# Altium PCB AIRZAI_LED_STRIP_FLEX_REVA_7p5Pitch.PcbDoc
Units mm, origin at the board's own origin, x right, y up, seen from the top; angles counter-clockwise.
Board outline 158.45 x 20.7 mm, 2 copper layers (Top Layer, Bottom Layer); 39 components, 40 nets, 198 pads, 42 vias.
Unrouted connection lines stored in the file: 63.
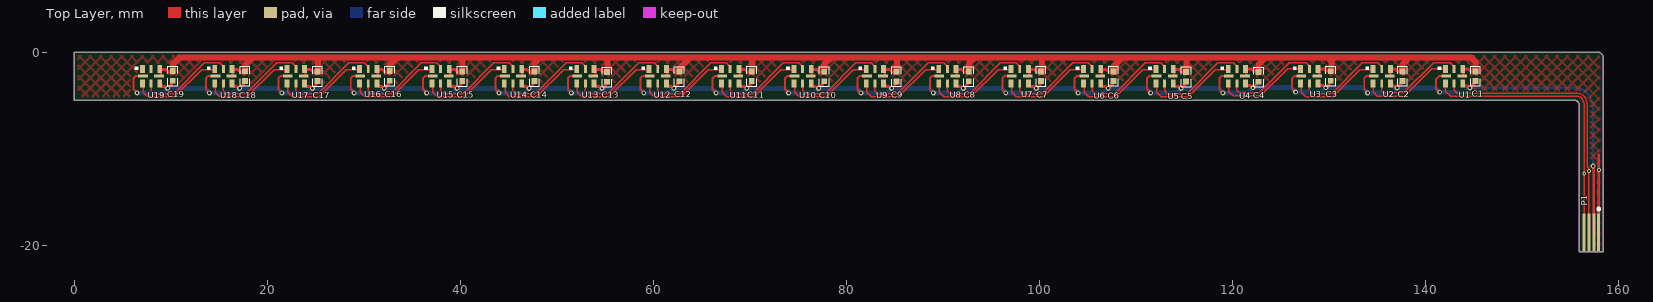
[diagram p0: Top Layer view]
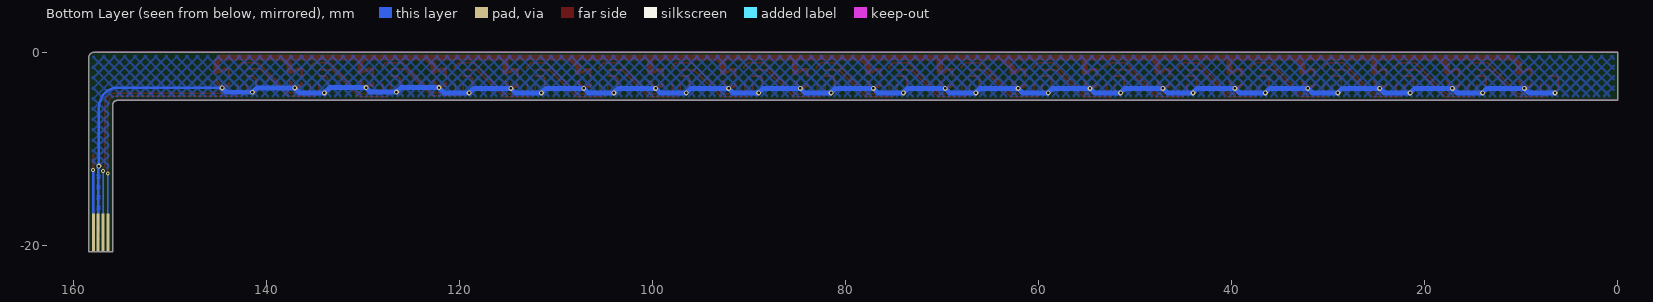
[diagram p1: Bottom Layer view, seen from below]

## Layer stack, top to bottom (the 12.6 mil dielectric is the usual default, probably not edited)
Top Solder: solder mask 0.0102, Solder Resist, Dk 3.5
Top Layer: signal copper 0.0356
Dielectric 1: dielectric 0.32, FR-4, Dk 4.8
Bottom Layer: signal copper 0.0356
Bottom Solder: solder mask 0.0102, Solder Resist, Dk 3.5

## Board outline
0,-5 0,0 157.814,0 cw(c157.814,-0.636) 158.45,-0.636 158.45,-20.7 155.95,-20.7 155.95,-5.5 ccw(c155.45,-5.5) 155.45,-5
board region "Layer Stack Region 1": 158.45,-14.093 158.45,-20.7 155.95,-20.7 155.95,-14.093
board region "Layer Stack Region 1": 155.95,-13.28 155.95,-5.5 155.94,-5.402 155.866,-5.222 155.728,-5.084 155.548,-5.01 155.45,-5 0,-5 0,0 157.814,0 157.941,0 158.174,-0.097 158.353,-0.276 158.45,-0.509 158.45,-0.636 158.45,-13.28
board region "Layer Stack Region 2": 155.95,-14.093 155.95,-13.28 158.45,-13.28 158.45,-14.093

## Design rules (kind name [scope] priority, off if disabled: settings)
Clearance Clearance_polygon_5V [OnLayer('Keep-Out Layer') vs (InNet('+5V') AND InPolygon)] p1: gap=0.254 ignorepadtopadclearanceinfootprint=FALSE
Clearance Clearance_POLYGON_KEEPOUT [(OnLayer('Keep-Out Layer')) vs (InNet('GND') AND InPolygon)] p2: gap=0.254 ignorepadtopadclearanceinfootprint=FALSE
Clearance [All] p3: gap=0.152 ignorepadtopadclearanceinfootprint=FALSE
MinimumSolderMaskSliver [All] p1: minsoldermaskwidth=0.025
PolygonConnect [All] p1: connectstyle=Direct reliefconductorwidth=0.254 reliefentries=4 polygonreliefangle="90 Angle" airgapwidth=0.254
RoomDefinition AIRZAI_LED_STRIP_FLEX_REVA_7p5Pitch [InComponentClass('AIRZAI_LED_STRIP_FLEX_REVA_7p5Pitch')] p1: confinementstyle=ConfineIn formatcopy=TRUE lockcomponents=FALSE outline -106.277,-135.212 266.087,-135.212 266.087,108.628 -106.277,108.628
RoutingVias [All] p1: holewidth=0.711 width=1.27 viastyle="Through Hole" minholewidth=0.203 minwidth=0.406 maxholewidth=0.711 maxwidth=1.27
SilkToSilkClearance [All] p1: silktosilkclearance=0.025
SilkToSolderMaskClearance [IsPad] p1: minsilkscreentomaskgap=0.051 clearancetoexposedcopper=TRUE
SolderMaskExpansion [All] p1: expansion=0.102
UnRoutedNet [All] p1: checkbadconnections=TRUE
Width [All] p1: maxlimit=2.54 minlimit=0.152 preferedwidth=0.254
26 further rules are at their usual default settings.

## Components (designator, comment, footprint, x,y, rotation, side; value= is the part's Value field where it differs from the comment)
C1 "0.1µF" 0402CAP 145.186,-2.5 r270 top
C2 "0.1µF" 0402CAP 137.64,-2.5 r270 top
C3 "0.1µF" 0402CAP 130.186,-2.483 r270 top
C4 "0.1µF" 0402CAP 122.724,-2.576 r270 top
C5 "0.1µF" 0402CAP 115.214,-2.559 r270 top
C6 "0.1µF" 0402CAP 107.686,-2.5 r270 top
C7 "0.1µF" 0402CAP 100.186,-2.508 r270 top
C8 "0.1µF" 0402CAP 92.686,-2.525 r270 top
C9 "0.1µF" 0402CAP 85.212,-2.538 r270 top
C10 "0.1µF" 0402CAP 77.712,-2.533 r270 top
C11 "0.1µF" 0402CAP 70.204,-2.508 r270 top
C12 "0.1µF" 0402CAP 62.712,-2.521 r270 top
C13 "0.1µF" 0402CAP 55.212,-2.576 r270 top
C14 "0.1µF" 0402CAP 47.697,-2.508 r270 top
C15 "0.1µF" 0402CAP 40.212,-2.508 r270 top
C16 "0.1µF" 0402CAP 32.696,-2.469 r270 top
C17 "0.1µF" 0402CAP 25.212,-2.508 r270 top
C18 "0.1µF" 0402CAP 17.712,-2.495 r270 top
C19 "0.1µF" 0402CAP 10.223,-2.471 r270 top
P1 "Header 4" FFC_4PADS 157.2,-18.7 r0 top
U1 "APA102-2020-256-8" APA102–2020 142.977,-2.5 r270 top
U2 "APA102-2020-256-8" APA102–2020 135.477,-2.5 r270 top
U3 "APA102-2020-256-8" APA102–2020 127.977,-2.5 r270 top
U4 "APA102-2020-256-8" APA102–2020 120.477,-2.5 r270 top
U5 "APA102-2020-256-8" APA102–2020 112.979,-2.5 r270 top
U6 "APA102-2020-256-8" APA102–2020 105.477,-2.5 r270 top
U7 "APA102-2020-256-8" APA102–2020 97.977,-2.5 r270 top
U8 "APA102-2020-256-8" APA102–2020 90.477,-2.5 r270 top
U9 "APA102-2020-256-8" APA102–2020 82.977,-2.5 r270 top
U10 "APA102-2020-256-8" APA102–2020 75.477,-2.5 r270 top
U11 "APA102-2020-256-8" APA102–2020 67.977,-2.5 r270 top
U12 "APA102-2020-256-8" APA102–2020 60.477,-2.5 r270 top
U13 "APA102-2020-256-8" APA102–2020 52.977,-2.5 r270 top
U14 "APA102-2020-256-8" APA102–2020 45.477,-2.5 r270 top
U15 "APA102-2020-256-8" APA102–2020 37.977,-2.5 r270 top
U16 "APA102-2020-256-8" APA102–2020 30.477,-2.5 r270 top
U17 "APA102-2020-256-8" APA102–2020 22.977,-2.5 r270 top
U18 "APA102-2020-256-8" APA102–2020 15.477,-2.5 r270 top
U19 "APA102-2020-256-8" APA102–2020 7.977,-2.5 r270 top

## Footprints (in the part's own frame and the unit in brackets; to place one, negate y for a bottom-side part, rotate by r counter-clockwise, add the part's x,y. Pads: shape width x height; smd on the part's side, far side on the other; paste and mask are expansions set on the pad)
0402CAP [mm] "Chip Capacitor, Body 1.1x0.5mm, IPC High Density"
  rect 0.6x0.6 smd: 1(-0.5,0) 2(0.5,0)
  silkscreen extent -1.02,-0.51 1.02,0.51, body extent -0.5,-0.3 0.5,0.3, height 0.19
APA102–2020 [mm]
  rect 0.8x0.5 smd: 1(-0.75,0.9) 3(-0.75,-0.9) 4(0.75,-0.9) 6(0.75,0.9)
  rect 0.8x0.3 smd: 2(-0.75,0) 5(0.75,0)
  rect 0.3x1 smd: 7(0,-0.83) 8(0,0.83)
  silkscreen extent -1.02,-1.7 -0.63,-1.32, body extent -1,-1 1,1, height 0.94
FFC_4PADS [mm] "(0.50mm"
  rect 0.3x4 smd: 1(0.75,0) 2(0.25,0) 3(-0.25,0) 4(-0.75,0)
  rect 0.3x4 smd far side: 1(0.75,0) 2(0.25,0) 3(-0.25,0) 4(-0.75,0)
  silkscreen extent 0.64,2.31 0.89,2.56

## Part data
C1 C2 C3 C4 C5 C6 C7 C8 C9 C10 C11 C12 C13 C14 C15 C16 C17 C18 C19: library part C0402-100n, "Capacitor, X7R, ±10%", Case-EIA=0402, Case-Metric=1005, Manufacturer=TDK, Manufacturer Part Number=C1005X7R1C104K, Rated Voltage="16 V", Supplier Part Number 1=445-4952-2-ND, Tolerance=±20%
P1: "Header, 4-Pin"
U1 U2 U3 U4 U5 U6 U7 U8 U9 U10 U11 U12 U13 U14 U15 U16 U17 U18 U19: "DotStar Micro LEDs", Package="SOIC-20 Adafruit Industries"

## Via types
v1: diameter 0.508, hole 0.254, Top Layer to Bottom Layer, tented both sides, 39 vias
v2: diameter 0.406, hole 0.203, Top Layer to Bottom Layer, tented both sides, 3 vias

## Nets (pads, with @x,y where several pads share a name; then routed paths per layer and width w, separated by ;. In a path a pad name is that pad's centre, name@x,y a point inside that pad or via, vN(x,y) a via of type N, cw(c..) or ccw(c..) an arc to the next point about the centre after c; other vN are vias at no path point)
+5V: C1.1 C2.1 C3.1 C4.1 C5.1 C6.1 C7.1 C8.1 C9.1 C10.1 C11.1 C12.1 C13.1 C14.1 C15.1 C16.1 C17.1 C18.1 C19.1 P1.1 U1.1 U1.8 U2.1 U2.8 U3.1 U3.8 U4.1 U4.8 U5.1 U5.8 U6.1 U6.8 U7.1 U7.8 U8.1 U8.8 U9.1 U9.8 U10.1 U10.8 U11.1 U11.8 U12.1 U12.8 U13.1 U13.8 U14.1 U14.8 U15.1 U15.8 U16.1 U16.8 U17.1 U17.8 U18.1 U18.8 U19.1 U19.8 | length 236
  Top Layer w0.254: U19.8@8.976,-2.46 U19.1@8.976,-1.809 ; U18.8@16.449,-2.5 U18.1@16.449,-1.809 ; U17.8@23.976,-2.46 U17.1@23.976,-1.809 ; U16.8@31.446,-2.5 U16.1@31.446,-1.809 ; U15.8@38.976,-2.46 U15.1@38.976,-1.809 ; U14.8@46.447,-2.5 U14.1@46.447,-1.809 ; U13.8@53.976,-2.46 U13.1@53.976,-1.809 ; U12.8@61.449,-2.5 U12.1@61.449,-1.809 ; U11.8@68.976,-2.46 U11.1@68.976,-1.809 ; U10.8@76.449,-2.5 U10.1@76.449,-1.809 ; U9.8@83.976,-2.46 U9.1@83.976,-1.809 ; U8.8@91.449,-2.5 U8.1@91.449,-1.809 ; U7.8@98.976,-2.46 U7.1@98.976,-1.809 ; U6.8@106.449,-2.5 U6.1@106.449,-1.809 ; U5.8@113.979,-2.46 U5.1@113.979,-1.809 ; U4.8@121.379,-2.482 121.426,-2.482 121.449,-2.459 U4.1@121.449,-1.732 ; U3.8@128.976,-2.482 128.999,-2.459 U3.1@128.999,-1.732 ; U2.8 136.354,-2.5 136.377,-2.477 U2.1 ; U1.8@143.9,-2.5 143.923,-2.477 U1.1@143.923,-1.75 ; P1.1@157.95,-18.7 157.95,-12.353 157.953,-12.351 157.953,-12.243 v2(157.982,-12.214) 157.982,-10.613
  Top Layer w0.305: U19.1@8.976,-1.809 9.498,-1.809 9.748,-2.059 C19.1@10.262,-2.059 ; U18.1@16.449,-1.809 16.948,-1.809 17.198,-2.059 C18.1@17.712,-2.059 ; U17.1@23.976,-1.809 24.498,-1.809 24.748,-2.059 C17.1@25.262,-2.059 ; U16.1@31.446,-1.809 31.945,-1.809 32.195,-2.059 C16.1@32.71,-2.059 ; U15.1@38.976,-1.809 39.498,-1.809 39.748,-2.059 C15.1@40.262,-2.059 ; U14.1@46.447,-1.809 46.946,-1.809 47.196,-2.059 C14.1@47.711,-2.059 ; U13.1@53.976,-1.809 54.498,-1.809 54.748,-2.059 C13.1@55.262,-2.059 ; U12.1@61.449,-1.809 61.948,-1.809 62.198,-2.059 C12.1@62.712,-2.059 ; U11.1@68.976,-1.809 69.498,-1.809 69.748,-2.059 C11.1@70.262,-2.059 ; U10.1@76.449,-1.809 76.948,-1.809 77.198,-2.059 C10.1@77.712,-2.059 ; U9.1@83.976,-1.809 84.498,-1.809 84.748,-2.059 C9.1@85.262,-2.059 ; U8.1@91.449,-1.809 91.948,-1.809 92.198,-2.059 C8.1@92.712,-2.059 ; U7.1@98.976,-1.809 99.498,-1.809 99.748,-2.059 C7.1@100.262,-2.059 ; U6.1@106.449,-1.809 106.948,-1.809 107.198,-2.059 C6.1@107.712,-2.059 ; U5.1@113.979,-1.809 114.501,-1.809 114.751,-2.059 C5.1@115.265,-2.059 ; U4.1@121.449,-1.732 121.948,-1.732 122.198,-1.982 C4.1@122.712,-1.982 ; U3.1@128.999,-1.732 129.498,-1.732 129.748,-1.982 C3.1@130.262,-1.982 ; U2.1 136.876,-1.75 137.126,-2 C2.1 ; U1.1@143.923,-1.75 144.422,-1.75 144.672,-2 C1.1
  Top Layer w0.635: C19.1@10.262,-2.059 10.262,-1.19 10.264,-1.19 10.879,-0.575 115.265,-0.575 ; C18.1@17.712,-2.059 17.712,-1.322 18.459,-0.575 ; 25.114,-0.575 25.262,-0.723 C17.1@25.262,-2.059 ; C16.1@32.71,-2.059 32.71,-1.314 33.449,-0.575 ; 35.951,-0.575 40.124,-0.575 40.262,-0.713 C15.1@40.262,-2.059 ; C14.1@47.711,-2.059 47.711,-1.134 48.27,-0.575 49.611,-0.575 ; 52.112,-0.575 55.206,-0.575 55.262,-0.632 C13.1@55.262,-2.059 ; C12.1@62.712,-2.059 62.712,-1.698 63.835,-0.575 ; 66.335,-0.575 70.08,-0.575 ; C11.1@70.262,-2.059 70.262,-0.758 70.08,-0.575 ; 70.262,-0.575 70.08,-0.575 ; C10.1@77.712,-2.059 77.712,-1.287 78.424,-0.575 ; C9.1@85.262,-2.059 85.262,-0.575 ; C8.1@92.712,-2.059 92.712,-1.183 93.319,-0.575 ; C7.1@100.262,-2.059 100.262,-0.711 100.127,-0.575 ; C6.1@107.712,-2.059 107.712,-1.47 108.606,-0.575 ; C5.1@115.265,-2.059 115.265,-0.575 ; C4.1@122.712,-1.982 122.712,-1.298 123.318,-0.691 ; 129.862,-0.575 130.262,-0.975 C3.1@130.262,-1.982 ; C2.1 137.64,-1.286 138.33,-0.595 138.31,-0.575 ; C1.1 145.186,-0.993 144.769,-0.575 115.265,-0.575 ; 100.127,-0.575 98.053,-0.575 100.127,-0.575
  Bottom Layer w0.254: P1.1@157.95,-18.7 157.95,-12.353 157.953,-12.351 157.953,-12.248 157.95,-12.246 v2(157.982,-12.214)
GND: C1.2 C2.2 C3.2 C4.2 C5.2 C6.2 C7.2 C8.2 C9.2 C10.2 C11.2 C12.2 C13.2 C14.2 C15.2 C16.2 C17.2 C18.2 C19.2 P1.2 U1.6 U1.7 U2.6 U2.7 U3.6 U3.7 U4.6 U4.7 U5.6 U5.7 U6.6 U6.7 U7.6 U7.7 U8.6 U8.7 U9.6 U9.7 U10.6 U10.7 U11.6 U11.7 U12.6 U12.7 U13.6 U13.7 U14.6 U14.7 U15.6 U15.7 U16.6 U16.7 U17.6 U17.7 U18.6 U18.7 U19.6 U19.7 | length 266.7
  Top Layer w0.203: v1(6.523,-4.22) 6.165,-3.863 6.165,-2.7 6.365,-2.5 U19.7 ; v1(14.023,-4.22) 13.665,-3.863 13.665,-2.7 13.865,-2.5 U18.7 ; v1(21.523,-4.22) 21.165,-3.863 21.165,-2.7 21.365,-2.5 U17.7 ; v1(29.023,-4.22) 28.665,-3.863 28.665,-2.7 28.865,-2.5 U16.7 ; v1(36.523,-4.22) 36.165,-3.863 36.165,-2.7 36.365,-2.5 U15.7 ; v1(44.023,-4.22) 43.665,-3.863 43.665,-2.7 43.865,-2.5 U14.7 ; v1(51.523,-4.22) 51.165,-3.863 51.165,-2.7 51.365,-2.5 U13.7 ; v1(59.023,-4.22) 58.665,-3.863 58.665,-2.7 58.865,-2.5 U12.7 ; v1(66.523,-4.22) 66.165,-3.863 66.165,-2.7 66.365,-2.5 U11.7 ; v1(74.023,-4.22) 73.665,-3.863 73.665,-2.7 73.865,-2.5 U10.7 ; v1(81.523,-4.22) 81.165,-3.863 81.165,-2.7 81.365,-2.5 U9.7 ; v1(89.023,-4.22) 88.665,-3.863 88.665,-2.7 88.865,-2.5 U8.7 ; v1(96.523,-4.22) 96.165,-3.863 96.165,-2.7 96.365,-2.5 U7.7 ; v1(104.023,-4.22) 103.665,-3.863 103.665,-2.7 103.865,-2.5 U6.7 ; v1(111.525,-4.22) 111.168,-3.863 111.168,-2.7 111.368,-2.5 U5.7 ; v1(119.023,-4.22) 118.665,-3.863 118.665,-2.7 118.865,-2.5 U4.7 ; v1(126.548,-4.144) 126.191,-3.787 126.191,-2.725 126.416,-2.5 U3.7@127.096,-2.5 ; v1(134.023,-4.22) 133.665,-3.863 133.665,-2.7 133.865,-2.5 U2.7 ; v1(141.472,-4.162) 141.115,-3.804 141.115,-2.813 141.427,-2.5 U1.7@142.037,-2.5
  Top Layer w0.254: v1@157.421,-11.856 v1(157.372,-11.807) 157.372,-12.061 157.45,-12.139 P1.2@157.45,-18.7
  Top Layer w0.305: U19.6@8.999,-3.309 8.999,-3.459 9.097,-3.556 9.431,-3.556 9.638,-3.763 v1(9.693,-3.763) 10.115,-3.342 10.115,-3.206 C19.2@10.262,-3.059 ; U18.6@16.449,-3.309 16.449,-3.459 16.546,-3.556 16.881,-3.556 17.088,-3.763 v1(17.143,-3.763) 17.564,-3.342 17.564,-3.206 C18.2@17.712,-3.059 ; U17.6@23.999,-3.309 23.999,-3.459 24.097,-3.556 24.431,-3.556 24.638,-3.763 v1(24.693,-3.763) 25.115,-3.342 25.115,-3.206 C17.2@25.262,-3.059 ; U16.6@31.446,-3.309 31.446,-3.459 31.544,-3.556 31.879,-3.556 32.086,-3.763 v1(32.141,-3.763) 32.562,-3.342 32.562,-3.206 C16.2@32.71,-3.059 ; U15.6@38.999,-3.309 38.999,-3.459 39.097,-3.556 39.431,-3.556 39.638,-3.763 v1(39.693,-3.763) 40.115,-3.342 40.115,-3.206 C15.2@40.262,-3.059 ; U14.6@46.447,-3.309 46.447,-3.459 46.545,-3.556 46.88,-3.556 47.087,-3.763 v1(47.142,-3.763) 47.563,-3.342 47.563,-3.206 C14.2@47.711,-3.059 ; U13.6@53.999,-3.309 53.999,-3.459 54.097,-3.556 54.431,-3.556 54.638,-3.763 v1(54.693,-3.763) 55.115,-3.342 55.115,-3.206 C13.2@55.262,-3.059 ; U12.6@61.449,-3.309 61.449,-3.459 61.546,-3.556 61.881,-3.556 62.088,-3.763 v1(62.143,-3.763) 62.564,-3.342 62.564,-3.206 C12.2@62.712,-3.059 ; U11.6@68.999,-3.309 68.999,-3.459 69.097,-3.556 69.431,-3.556 69.638,-3.763 v1(69.693,-3.763) 70.115,-3.342 70.115,-3.206 C11.2@70.262,-3.059 ; U10.6@76.449,-3.309 76.449,-3.459 76.546,-3.556 76.881,-3.556 77.088,-3.763 v1(77.143,-3.763) 77.564,-3.342 77.564,-3.206 C10.2@77.712,-3.059 ; U9.6@83.999,-3.309 83.999,-3.459 84.097,-3.556 84.431,-3.556 84.638,-3.763 v1(84.693,-3.763) 85.115,-3.342 85.115,-3.206 C9.2@85.262,-3.059 ; U8.6@91.449,-3.309 91.449,-3.459 91.546,-3.556 91.881,-3.556 92.088,-3.763 v1(92.143,-3.763) 92.564,-3.342 92.564,-3.206 C8.2@92.712,-3.059 ; U7.6@98.999,-3.309 98.999,-3.459 99.097,-3.556 99.431,-3.556 99.638,-3.763 v1(99.693,-3.763) 100.115,-3.342 100.115,-3.206 C7.2@100.262,-3.059 ; U6.6@106.449,-3.309 106.449,-3.459 106.546,-3.556 106.881,-3.556 107.088,-3.763 v1(107.143,-3.763) 107.564,-3.342 107.564,-3.206 C6.2@107.712,-3.059 ; U5.6@114.002,-3.309 114.002,-3.459 114.099,-3.556 114.434,-3.556 114.641,-3.763 v1(114.696,-3.763) 115.117,-3.342 115.117,-3.206 C5.2@115.265,-3.059 ; U4.6@121.449,-3.232 121.449,-3.382 121.546,-3.48 121.881,-3.48 122.088,-3.687 v1(122.143,-3.687) 122.564,-3.266 122.564,-3.13 C4.2@122.712,-2.982 ; U3.6@128.999,-3.232 128.999,-3.382 129.097,-3.48 129.431,-3.48 129.638,-3.687 v1(129.693,-3.687) 130.115,-3.266 130.115,-3.13 C3.2@130.262,-2.982 ; U2.6 136.377,-3.4 136.474,-3.498 136.809,-3.498 137.016,-3.705 v1(137.071,-3.705) 137.492,-3.283 137.492,-3.148 C2.2 ; U1.6@143.923,-3.25 143.923,-3.4 144.021,-3.498 144.355,-3.498 144.562,-3.705 v1(144.617,-3.705) 145.039,-3.283 145.039,-3.148 C1.2
  Bottom Layer w0.254: v1(144.617,-3.705) 155.498,-3.705 cw(c155.498,-5.466) 156.743,-4.22 cw(c155.225,-5.739) 157.372,-5.739 v1(157.372,-11.807) ; P1.2@157.45,-18.7 157.45,-12.064
  Bottom Layer w0.508: v1(6.523,-4.22) 9.236,-4.22 v1(9.693,-3.763) 13.565,-3.763 v1(14.023,-4.22) 16.686,-4.22 v1(17.143,-3.763) 21.065,-3.763 v1(21.523,-4.22) 24.236,-4.22 v1(24.693,-3.763) 28.565,-3.763 v1(29.023,-4.22) 31.683,-4.22 v1(32.141,-3.763) 36.065,-3.763 v1(36.523,-4.22) 39.236,-4.22 v1(39.693,-3.763) 43.565,-3.763 v1(44.023,-4.22) 46.684,-4.22 v1(47.142,-3.763) 51.065,-3.763 v1(51.523,-4.22) 54.236,-4.22 v1(54.693,-3.763) 58.565,-3.763 v1(59.023,-4.22) 61.686,-4.22 v1(62.143,-3.763) 66.065,-3.763 v1(66.523,-4.22) 69.236,-4.22 v1(69.693,-3.763) 73.565,-3.763 v1(74.023,-4.22) 76.686,-4.22 v1(77.143,-3.763) 81.065,-3.763 v1(81.523,-4.22) 84.236,-4.22 v1(84.693,-3.763) 88.565,-3.763 v1(89.023,-4.22) 91.686,-4.22 v1(92.143,-3.763) 96.065,-3.763 v1(96.523,-4.22) 99.236,-4.22 v1(99.693,-3.763) 103.565,-3.763 v1(104.023,-4.22) 106.686,-4.22 v1(107.143,-3.763) 111.068,-3.763 v1(111.525,-4.22) 114.239,-4.22 v1(114.696,-3.763) 118.565,-3.763 v1(119.023,-4.22) 121.61,-4.22 v1(122.143,-3.687) 126.091,-3.687 v1(126.548,-4.144) 129.236,-4.144 v1(129.693,-3.687) 133.489,-3.687 v1(134.023,-4.22) 136.555,-4.22 v1(137.071,-3.705) 141.015,-3.705 v1(141.472,-4.162) 144.16,-4.162 v1(144.617,-3.705)
LED_CLK_IN: P1.3 U1.5 | length 35
  Top Layer w0.152: U1.5 142.977,-3.965 143.301,-4.289 155.83,-4.289 cw(c155.83,-5.069) 156.382,-4.517 cw(c155.401,-5.499) 156.788,-5.499 156.788,-11.765 ccw(c157.135,-11.765) 156.89,-12.01 cw(c156.744,-12.156) 156.95,-12.156 v2(156.95,-12.315) P1.3@156.95,-18.7
  Bottom Layer w0.152: P1.3@156.95,-18.7 v2(156.95,-12.315)
LED_CLK_OUT1: U1.2 U2.5 | length 10
  Top Layer w0.152: U2.5 135.477,-4.031 135.684,-4.238 137.731,-4.238 140.848,-1.121 142.572,-1.121 142.977,-1.526 U1.2
LED_CLK_OUT2: U2.2 U3.5 | length 10.1
  Top Layer w0.152: U3.5@127.973,-3.25 127.973,-4.017 128.252,-4.297 130.3,-4.297 133.475,-1.121 135.089,-1.121 135.553,-1.585 U2.2@135.553,-1.75
LED_CLK_OUT3: U3.2 U4.5 | length 10.1
  Top Layer w0.152: U4.5 120.477,-3.941 120.756,-4.22 122.803,-4.22 125.903,-1.121 127.665,-1.121 128.053,-1.509 U3.2@128.053,-1.732
LED_CLK_OUT4: U4.2 U5.5 | length 10.1
  Top Layer w0.152: U5.5 112.979,-4.017 113.258,-4.297 115.306,-4.297 118.481,-1.121 120.089,-1.121 120.553,-1.585 U4.2@120.553,-1.75
LED_CLK_OUT5: U5.2 U6.5 | length 10.1
  Top Layer w0.152: U6.5 105.477,-4.017 105.756,-4.297 107.803,-4.297 110.979,-1.121 112.592,-1.121 113.055,-1.585 U5.2@113.055,-1.75
LED_CLK_OUT6: U6.2 U7.5 | length 10.1
  Top Layer w0.152: U7.5 97.977,-4.017 98.256,-4.297 100.303,-4.297 103.479,-1.121 105.089,-1.121 105.553,-1.585 U6.2@105.553,-1.75
LED_CLK_OUT7: U7.2 U8.5 | length 10.1
  Top Layer w0.152: U8.5 90.477,-4.017 90.756,-4.297 92.803,-4.297 95.979,-1.121 97.589,-1.121 98.053,-1.585 U7.2@98.053,-1.75
LED_CLK_OUT8: U8.2 U9.5 | length 10.1
  Top Layer w0.152: U9.5 82.977,-4.017 83.256,-4.297 85.303,-4.297 88.479,-1.121 90.089,-1.121 90.553,-1.585 U8.2@90.553,-1.75
LED_CLK_OUT9: U9.2 U10.5 | length 10.1
  Top Layer w0.152: U10.5 75.477,-4.017 75.756,-4.297 77.803,-4.297 80.979,-1.121 82.589,-1.121 83.053,-1.585 U9.2@83.053,-1.75
LED_CLK_OUT10: U10.2 U11.5 | length 10.1
  Top Layer w0.152: U11.5 67.977,-4.017 68.256,-4.297 70.303,-4.297 73.479,-1.121 75.089,-1.121 75.553,-1.585 U10.2@75.553,-1.75
LED_CLK_OUT11: U11.2 U12.5 | length 10.1
  Top Layer w0.152: U12.5 60.477,-4.017 60.756,-4.297 62.803,-4.297 65.979,-1.121 67.589,-1.121 68.053,-1.585 U11.2@68.053,-1.75
LED_CLK_OUT12: U12.2 U13.5 | length 10.1
  Top Layer w0.152: U13.5 52.977,-4.017 53.256,-4.297 55.303,-4.297 58.479,-1.121 60.089,-1.121 60.553,-1.585 U12.2@60.553,-1.75
LED_CLK_OUT13: U13.2 U14.5 | length 10.1
  Top Layer w0.152: U14.5@45.475,-3.25 45.475,-4.017 45.754,-4.297 47.802,-4.297 50.977,-1.121 52.589,-1.121 53.053,-1.585 U13.2@53.053,-1.75
LED_CLK_OUT14: U14.2 U15.5 | length 10.1
  Top Layer w0.152: U15.5@37.98,-3.25 37.98,-4.017 38.26,-4.297 40.307,-4.297 43.483,-1.121 45.089,-1.121 45.553,-1.585 U14.2@45.553,-1.75
LED_CLK_OUT15: U15.2 U16.5 | length 10.1
  Top Layer w0.152: U16.5@30.474,-3.25 30.474,-4.017 30.753,-4.297 32.801,-4.297 35.976,-1.121 37.589,-1.121 38.053,-1.585 U15.2@38.053,-1.75
LED_CLK_OUT16: U16.2 U17.5 | length 10.1
  Top Layer w0.152: U17.5 22.977,-4.017 23.256,-4.297 25.303,-4.297 28.479,-1.121 30.089,-1.121 30.553,-1.585 U16.2@30.553,-1.75
LED_CLK_OUT17: U17.2 U18.5 | length 10.1
  Top Layer w0.152: U18.5 15.477,-4.017 15.756,-4.297 17.803,-4.297 20.979,-1.121 22.589,-1.121 23.053,-1.585 U17.2@23.053,-1.75
LED_CLK_OUT18: U18.2 U19.5 | length 10.1
  Top Layer w0.152: U19.5 7.977,-4.017 8.256,-4.297 10.303,-4.297 13.479,-1.121 15.089,-1.121 15.553,-1.585 U18.2@15.553,-1.75
LED_SDI: P1.4 U1.4 | length 35.3
  Top Layer w0.152: U1.4 142.077,-4.055 142.615,-4.594 155.76,-4.594 cw(c155.76,-5.114) 156.128,-4.746 cw(c155.35,-5.524) 156.45,-5.524 P1.4@156.45,-18.7
  Bottom Layer w0.152: P1.4@156.45,-18.7 156.458,-18.692 v2(156.458,-12.595)
LED_SDO_1: U1.3 U2.4 | length 9.7
  Top Layer w0.152: U2.4 134.577,-4.106 135.039,-4.568 137.833,-4.568 140.651,-1.75 U1.3
LED_SDO_2: U2.3 U3.4 | length 9.7
  Top Layer w0.152: U3.4@127.145,-3.309 127.145,-4.165 127.607,-4.627 130.401,-4.627 133.219,-1.809 U2.3@134.653,-1.809
LED_SDO_3: U3.3 U4.4 | length 9.7
  Top Layer w0.152: U4.4@119.649,-3.232 119.649,-4.088 120.111,-4.551 122.905,-4.551 125.723,-1.732 U3.3@127.153,-1.732
LED_SDO_4: U4.3 U5.4 | length 9.7
  Top Layer w0.152: U5.4@112.151,-3.309 112.151,-4.165 112.614,-4.627 115.408,-4.627 118.226,-1.809 U4.3@119.653,-1.809
LED_SDO_5: U5.3 U6.4 | length 9.7
  Top Layer w0.152: U6.4@104.649,-3.309 104.649,-4.165 105.111,-4.627 107.905,-4.627 110.723,-1.809 U5.3@112.155,-1.809
LED_SDO_6: U6.3 U7.4 | length 9.7
  Top Layer w0.152: U7.4@97.149,-3.309 97.149,-4.165 97.611,-4.627 100.405,-4.627 103.223,-1.809 U6.3@104.653,-1.809
LED_SDO_7: U7.3 U8.4 | length 9.7
  Top Layer w0.152: U8.4@89.649,-3.309 89.649,-4.165 90.111,-4.627 92.905,-4.627 95.723,-1.809 U7.3@97.153,-1.809
LED_SDO_8: U8.3 U9.4 | length 9.7
  Top Layer w0.152: U9.4@82.149,-3.309 82.149,-4.165 82.611,-4.627 85.405,-4.627 88.223,-1.809 U8.3@89.653,-1.809
LED_SDO_9: U9.3 U10.4 | length 9.7
  Top Layer w0.152: U10.4@74.649,-3.309 74.649,-4.165 75.111,-4.627 77.905,-4.627 80.723,-1.809 U9.3@82.153,-1.809
LED_SDO_10: U10.3 U11.4 | length 9.7
  Top Layer w0.152: U11.4@67.149,-3.309 67.149,-4.165 67.611,-4.627 70.405,-4.627 73.223,-1.809 U10.3@74.653,-1.809
LED_SDO_11: U11.3 U12.4 | length 9.7
  Top Layer w0.152: U12.4@59.649,-3.309 59.649,-4.165 60.111,-4.627 62.905,-4.627 65.723,-1.809 U11.3@67.153,-1.809
LED_SDO_12: U12.3 U13.4 | length 9.7
  Top Layer w0.152: U13.4@52.149,-3.309 52.149,-4.165 52.611,-4.627 55.405,-4.627 58.223,-1.809 U12.3@59.653,-1.809
LED_SDO_13: U13.3 U14.4 | length 9.7
  Top Layer w0.152: U14.4@44.647,-3.309 44.647,-4.165 45.11,-4.627 47.904,-4.627 50.722,-1.809 U13.3@52.153,-1.809
LED_SDO_14: U14.3 U15.4 | length 9.7
  Top Layer w0.152: U15.4@37.153,-3.309 37.153,-4.165 37.615,-4.627 40.409,-4.627 43.227,-1.809 U14.3@44.653,-1.809
LED_SDO_15: U15.3 U16.4 | length 9.7
  Top Layer w0.152: U16.4@29.646,-3.309 29.646,-4.165 30.109,-4.627 32.903,-4.627 35.721,-1.809 U15.3@37.153,-1.809
LED_SDO_16: U16.3 U17.4 | length 10
  Top Layer w0.152: U17.4@22.149,-3.309 22.149,-4.165 22.611,-4.627 25.405,-4.627 26.177,-3.854 ; 25.996,-4.035 28.222,-1.809 U16.3@29.653,-1.809
LED_SDO_17: U17.3 U18.4 | length 9.7
  Top Layer w0.152: U18.4@14.649,-3.309 14.649,-4.165 15.111,-4.627 17.905,-4.627 20.723,-1.809 U17.3@22.153,-1.809
LED_SDO_18: U18.3 U19.4 | length 9.7
  Top Layer w0.152: U19.4@7.149,-3.309 7.149,-4.165 7.611,-4.627 10.405,-4.627 13.223,-1.809 U18.3@14.653,-1.809
pads on no net: U19.2 U19.3
copper on no net: | length 0.2
  Top Layer w0.152: 8.053,-1.75 8.053,-1.585

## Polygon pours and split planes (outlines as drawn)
GND on Bottom Layer "gnd_bot" (hatched 45Degree grid 0.762 track 0.241, remove dead copper, pour order 0): 0,-5 0,0 157.814,0 cw(c157.814,-0.636) 158.45,-0.636 158.45,-20.7 155.95,-20.7 155.95,-5.5 ccw(c155.45,-5.5) 155.45,-5
+5V on Top Layer "Top Layer-+5V" (hatched 45Degree grid 0.762 track 0.241, remove dead copper, pour order 1): 0,-5 0,0 157.814,0 cw(c157.814,-0.636) 158.45,-0.636 158.45,-20.7 155.95,-20.7 155.95,-5.5 ccw(c155.45,-5.5) 155.45,-5

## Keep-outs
Keep-Out Layer:
  lines w0.127: 155.45,-5 cw(c155.45,-5.5) 155.95,-5.5 155.95,-20.7 158.45,-20.7 158.45,-0.636 ccw(c157.814,-0.636) 157.814,0 155.95,0 147.45,0 0,0 0,-5 155.45,-5 ; 155.45,-5 155.45,-5

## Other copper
Top Layer:
  pour cut-out: 21.515,-1.121 21.523,-1.114 24.698,-1.114 24.698,-4.009 24.69,-4.017 21.523,-4.017 21.523,-1.129
  pour cut-out: 14.011,-1.121 14.019,-1.114 17.194,-1.114 17.194,-4.009 17.186,-4.017 14.019,-4.017 14.019,-1.129
  pour cut-out: 6.519,-1.121 6.527,-1.114 9.702,-1.114 9.702,-4.009 9.694,-4.017 6.527,-4.017 6.527,-1.129
  pour cut-out: 51.515,-1.121 51.523,-1.114 54.698,-1.114 54.698,-4.009 54.69,-4.017 51.523,-4.017 51.523,-1.129
  pour cut-out: 44.01,-1.121 44.018,-1.114 47.193,-1.114 47.193,-4.009 47.185,-4.017 44.018,-4.017 44.018,-1.129
  pour cut-out: 29.015,-1.121 29.023,-1.114 32.198,-1.114 32.198,-4.009 32.19,-4.017 29.023,-4.017 29.023,-1.129
  pour cut-out: 36.521,-1.121 36.529,-1.114 39.704,-1.114 39.704,-4.009 39.696,-4.017 36.529,-4.017 36.529,-1.129
  pour cut-out: 81.515,-1.121 81.523,-1.114 84.698,-1.114 84.698,-4.009 84.69,-4.017 81.523,-4.017 81.523,-1.129
  pour cut-out: 74.011,-1.121 74.019,-1.114 77.194,-1.114 77.194,-4.009 77.186,-4.017 74.019,-4.017 74.019,-1.129
  pour cut-out: 59.015,-1.121 59.023,-1.114 62.198,-1.114 62.198,-4.009 62.19,-4.017 59.023,-4.017 59.023,-1.129
  pour cut-out: 66.519,-1.121 66.527,-1.114 69.702,-1.114 69.702,-4.009 69.694,-4.017 66.527,-4.017 66.527,-1.129
  pour cut-out: 111.518,-1.121 111.525,-1.114 114.7,-1.114 114.7,-4.009 114.692,-4.017 111.525,-4.017 111.525,-1.129
  pour cut-out: 104.011,-1.121 104.019,-1.114 107.194,-1.114 107.194,-4.009 107.186,-4.017 104.019,-4.017 104.019,-1.129
  pour cut-out: 89.015,-1.121 89.023,-1.114 92.198,-1.114 92.198,-4.009 92.19,-4.017 89.023,-4.017 89.023,-1.129
  pour cut-out: 96.519,-1.121 96.527,-1.114 99.702,-1.114 99.702,-4.009 99.694,-4.017 96.527,-4.017 96.527,-1.129
  pour cut-out: 126.519,-1.121 126.527,-1.114 129.702,-1.114 129.702,-4.009 129.694,-4.017 126.527,-4.017 126.527,-1.129
  pour cut-out: 119.015,-1.121 119.023,-1.114 122.198,-1.114 122.198,-4.009 122.19,-4.017 119.023,-4.017 119.023,-1.129
  pour cut-out: 134.015,-1.121 134.023,-1.114 137.198,-1.114 137.198,-4.009 137.19,-4.017 134.023,-4.017 134.023,-1.129
  pour cut-out: 141.515,-1.121 141.523,-1.114 144.698,-1.114 144.698,-4.009 144.69,-4.017 141.523,-4.017 141.523,-1.129

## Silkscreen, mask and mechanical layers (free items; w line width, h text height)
Mechanical 1:
  lines w0.127: 0.025,-2.511 cw(c0.036,-2.511) 0.036,-2.5 147.45,-2.5 147.45,0 ; 151.817,-13.7 158.45,-13.7 ; 155.95,-1.317 155.95,0 ; 7.977,-2.741 7.977,-2.259 ; 7.977,-2.741 7.977,-2.259 ; 7.977,-2.741 7.977,-2.259 ; 7.977,-2.741 7.977,-2.259 ; 15.477,-2.741 15.477,-2.259 ; 15.477,-2.741 15.477,-2.259 ; 15.477,-2.741 15.477,-2.259 ; 15.477,-2.741 15.477,-2.259 ; 22.977,-2.741 22.977,-2.259 ; 22.977,-2.741 22.977,-2.259 ; 22.977,-2.741 22.977,-2.259 ; 22.977,-2.741 22.977,-2.259 ; 30.477,-2.741 30.477,-2.259 ; 30.477,-2.741 30.477,-2.259 ; 30.477,-2.741 30.477,-2.259 ; 30.477,-2.741 30.477,-2.259 ; 37.977,-2.741 37.977,-2.259 ; 37.977,-2.741 37.977,-2.259 ; 37.977,-2.741 37.977,-2.259 ; 37.977,-2.741 37.977,-2.259 ; 45.477,-2.741 45.477,-2.259 ; 45.477,-2.741 45.477,-2.259 ; 45.477,-2.741 45.477,-2.259 ; 45.477,-2.741 45.477,-2.259 ; 52.977,-2.741 52.977,-2.259 ; 52.977,-2.741 52.977,-2.259 ; 52.977,-2.741 52.977,-2.259 ; 52.977,-2.741 52.977,-2.259 ; 60.477,-2.741 60.477,-2.259 ; 60.477,-2.741 60.477,-2.259 ; 60.477,-2.741 60.477,-2.259 ; 60.477,-2.741 60.477,-2.259 ; 67.977,-2.741 67.977,-2.259 ; 67.977,-2.741 67.977,-2.259 ; 67.977,-2.741 67.977,-2.259 ; 67.977,-2.741 67.977,-2.259 ; 75.477,-2.741 75.477,-2.259 ; 75.477,-2.741 75.477,-2.259 ; 75.477,-2.741 75.477,-2.259 ; 75.477,-2.741 75.477,-2.259 ; 82.977,-2.741 82.977,-2.259 ; 82.977,-2.741 82.977,-2.259 ; 82.977,-2.741 82.977,-2.259 ; 82.977,-2.741 82.977,-2.259 ; 90.477,-2.741 90.477,-2.259 ; 90.477,-2.741 90.477,-2.259 ; 90.477,-2.741 90.477,-2.259 ; 90.477,-2.741 90.477,-2.259 ; 97.977,-2.741 97.977,-2.259 ; 97.977,-2.741 97.977,-2.259 ; 97.977,-2.741 97.977,-2.259 ; 97.977,-2.741 97.977,-2.259 ; 105.477,-2.741 105.477,-2.259 ; 105.477,-2.741 105.477,-2.259 ; 105.477,-2.741 105.477,-2.259 ; 105.477,-2.741 105.477,-2.259 ; 112.977,-2.741 112.977,-2.259 ; 112.977,-2.741 112.977,-2.259 ; 112.977,-2.741 112.977,-2.259 ; 112.977,-2.741 112.977,-2.259 ; 120.477,-2.741 120.477,-2.259 ; 120.477,-2.741 120.477,-2.259 ; 120.477,-2.741 120.477,-2.259 ; 120.477,-2.741 120.477,-2.259 ; 127.977,-2.741 127.977,-2.259 ; 127.977,-2.741 127.977,-2.259 ; 127.977,-2.741 127.977,-2.259 ; 127.977,-2.741 127.977,-2.259 ; 135.477,-2.741 135.477,-2.259 ; 135.477,-2.741 135.477,-2.259 ; 135.477,-2.741 135.477,-2.259 ; 135.477,-2.741 135.477,-2.259 ; 142.977,-2.741 142.977,-2.259 ; 142.977,-2.741 142.977,-2.259 ; 142.977,-2.741 142.977,-2.259 ; 142.977,-2.741 142.977,-2.259 ; 142.977,-2.741 142.977,-2.259 ; 142.977,-2.741 142.977,-2.259 ; 142.977,-2.741 142.977,-2.259 ; 142.977,-2.741 142.977,-2.259
Mechanical 4:
  lines w0.127: 155.45,-5 cw(c155.45,-5.5) 155.95,-5.5 155.95,-20.7 158.45,-20.7 158.45,-0.636 ccw(c157.814,-0.636) 157.814,0 155.95,0 147.45,0 0,0 0,-5 155.45,-5 ; 155.45,-5 155.45,-5
Drill Drawing:
  text "PWB, LED STRIP FLEX" at 184.848,-116.107 h4
  text "PWB-020218-001" at 189.598,-124.382 h3.25
  text "1" at 251.198,-125.882 h2
  text "1" at 246.398,-125.982 h2
Mechanical 17:
  text "PWB, LED STRIP FLEX" at 185.93,-118.002 h4
  text "PWA-020218-001" at 190.858,-125.393 h3.25
  text "1" at 246.198,-125.682 h1.5
  text "1" at 250.998,-125.682 h1.5
  text "NOTES: /  / 1. ALL ASSEMBLY MATERIALS TO BE RoHS COMPLIANT. /  / 2. MATERIAL: /           • FLEXIBLE METAL CLAD DIELECTRIC IAW                 /             IPC-4204/11 E1E2 O0/0 CU W7 T/T /           • STIFFENER IAW IPC-4203/1-E1E8M1 /  / 3. FINISH:  IMMERSION GOLD /  / ALL EXPOSED CONDUCTIVE PATTERN AREAS NOT COVERED WITH COVERLAY MATERIAL OR OTHER PLATING  / SHALL BE IMMERSION GOLD (0.000030-0.000090 mm) OVER ELECTROLESS NICKEL (0.001-0.006 mm). /  / 4. LEGEND SHALL BE WHITE, PERMANENT, ORGANIC, NON-CONDUCTIVE UV OR EPOXY TYPE INK APPLIED  / TO THE TOP SIDE OF THE BOARD. THERE SHALL BE NO LEGEND ON ANY SOLDERABLE COMPONENT LAND. /  / 5. ALL ASSEMBLY MATERIALS TO BE RoHS COMPLIANT. /  / 6. ANY LABELS OR COMPOSITION OF, APPLIED TO THE BOARD NEED TO BE APPROVIED BY AIRZAI /  / 7. MINIMUM TRACE WIDTHS: /           EXTERNAL: 0.203 mm  INTERNAL: N/A /  / 8. MINIMUM SPACE BETWEEN FEATURES: /          EXTERNAL: 0.15 mm  INTERNAL: N/A /  / 9. Overall Board Thickness: 0.3mm" at -101.448,-128.114 h2
Mechanical 18:
  lines w0.127: -112.137,-71.477 -107.057,-71.477 ; -112.137,-11.152 -107.057,-11.152 ; -112.137,49.173 -107.057,49.173 ; -48.637,-131.802 -48.637,-126.722 ; -48.637,104.418 -48.637,109.498 ; 14.863,-131.802 14.863,-126.722 ; 14.863,104.418 14.863,109.498 ; 78.363,-131.802 78.363,-126.722 ; 78.363,104.418 78.363,109.498 ; 141.863,-131.802 141.863,-126.722 ; 141.863,104.418 141.863,109.498 ; 149.462,-119.159 263.762,-119.159 ; 149.462,-113.019 176.657,-113.019 ; 149.462,-107.074 176.657,-107.074 ; 149.462,-101.719 176.657,-101.719 ; 149.483,-126.722 263.783,-126.722 ; 165.357,-126.804 165.357,-96.324 ; 176.657,-126.779 176.657,-96.299 ; 176.657,-109.839 263.759,-109.839 ; 185.292,-96.299 263.762,-96.299 ; 187.562,-96.299 149.462,-96.299 ; 205.363,-131.802 205.363,-126.722 ; 205.363,104.418 205.363,109.498 ; 254.202,-126.779 254.202,-119.159 ; 263.783,-96.242 263.783,-126.722 ; 263.783,-71.477 268.863,-71.477 ; 263.783,49.173 268.863,49.173 ; 113.902,-126.779 149.462,-126.779 ; 113.902,-126.779 149.462,-126.779 ; 113.902,-126.779 113.902,-96.299 149.462,-96.299 ; 149.462,-126.779 263.762,-126.779 ; 149.462,-126.779 263.762,-126.779 ; 149.462,-126.779 149.462,-96.299 ; 263.762,-126.779 263.762,-96.299 ; 263.762,-126.779 263.762,-96.299 ; 263.783,-126.722 263.783,104.418 -107.057,104.418 -107.057,-126.722 263.783,-126.722 ; -112.137,-131.802 -112.137,109.498 268.863,109.498 268.863,-131.802 -112.137,-131.802
  text "1" at -80.861,106.196 h1.78
  text "2" at -17.472,106.196 h1.78
  text "3" at 45.758,106.196 h1.78
  text "4" at 109.427,106.196 h1.78
  text "5" at 172.901,106.196 h1.78
  text "6" at 236.528,106.196 h1.78
  text "A" at -110.232,77.163 h1.78
  text "A" at 265.688,77.163 h1.78
  text "B" at -110.232,16.711 h1.78
  text "B" at 265.688,16.711 h1.78
  text "C" at -110.232,-43.614 h1.78
  text "C" at 265.688,-43.614 h1.78
  text "AIRZAI PROPRIETARY & CONFIDENTIAL" at 153.423,-93.482 h3.25
  text "DATE:" at 166.132,-97.879 h1.14
  text "ENGINEER:" at 150.032,-98.039 h1.14
  text "UNLESS OTHERWISE SPECIFIED" at 116.432,-99.579 h1.5
  text "21/01/19" at 166.319,-100.637 h1.5
  text "FD" at 154.931,-100.797 h2
  text "DIMENSIONS ARE IN MM" at 119.532,-102.779 h1.5
  text "PCB DESIGNER:" at 149.932,-103.332 h1.14
  text "DATE:" at 165.832,-103.379 h1.14
  text "D" at -110.232,-103.812 h1.78
  text "D" at 265.688,-103.812 h1.78
  text "AIRZAI" at 184.048,-104.782 h3.25
  text "TOLERANCES" at 124.632,-105.979 h1.5
  text "21/01/19" at 166.319,-106.087 h1.5
  text "DFM" at 154.261,-106.128 h2
  text "DATE:" at 165.832,-108.779 h1.14
  text "CHECK" at 149.932,-108.832 h1.14
  text "ANGULAR" at 136.932,-109.979 h1.5
  text "DECIMALS" at 116.532,-110.279 h1.5
  text "TITLE:" at 177.973,-111.457 h1.14
  text "FD" at 155.931,-111.797 h2
  text ".XX +/- .127MM" at 115.332,-114.279 h1.5
  text "+/-" at 136.632,-114.379 h1.5
  text "REL" at 150.232,-114.699 h1.14
  text "DATE:" at 166.232,-114.879 h1.14
  text "FD" at 155.681,-117.297 h2
  text ".XXX +/- .080MM" at 115.032,-118.379 h1.5
  text "REV:" at 254.772,-120.779 h1.14
  text "SCALE:" at 166.372,-120.799 h1.14
  text "DWG NO:" at 177.832,-120.999 h1.14
  text "SIZE" at 150.232,-121.079 h1.14
  text "B" at 155.407,-124.396 h3.05
  text "DO NOT SCALE DRAWING" at 116.432,-124.479 h1.8
  text "A" at 256.898,-124.882 h3.05
  text "1:1" at 167.607,-124.996 h3.05
  text "SHEET" at 240.432,-125.799 h1.14
  text "OF" at 247.132,-125.799 h1.14
  text "1" at -80.861,-130.024 h1.78
  text "2" at -17.472,-130.024 h1.78
  text "3" at 45.758,-130.024 h1.78
  text "4" at 109.427,-130.024 h1.78
  text "5" at 172.901,-130.024 h1.78
  text "6" at 236.528,-130.024 h1.78

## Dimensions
147.45,3.179 to 155.95,0 on Mechanical 1
0,0 to 147.45,0 on Mechanical 1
